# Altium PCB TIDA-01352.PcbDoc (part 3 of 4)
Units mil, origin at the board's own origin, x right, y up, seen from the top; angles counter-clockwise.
Board outline 6496.06 x 8661.42 mil, 4 copper layers (Top Layer, GND, PWR, Bottom Layer), stack 79.834 mil thick; 456 components, 240 nets, 1197 pads, 446 vias.
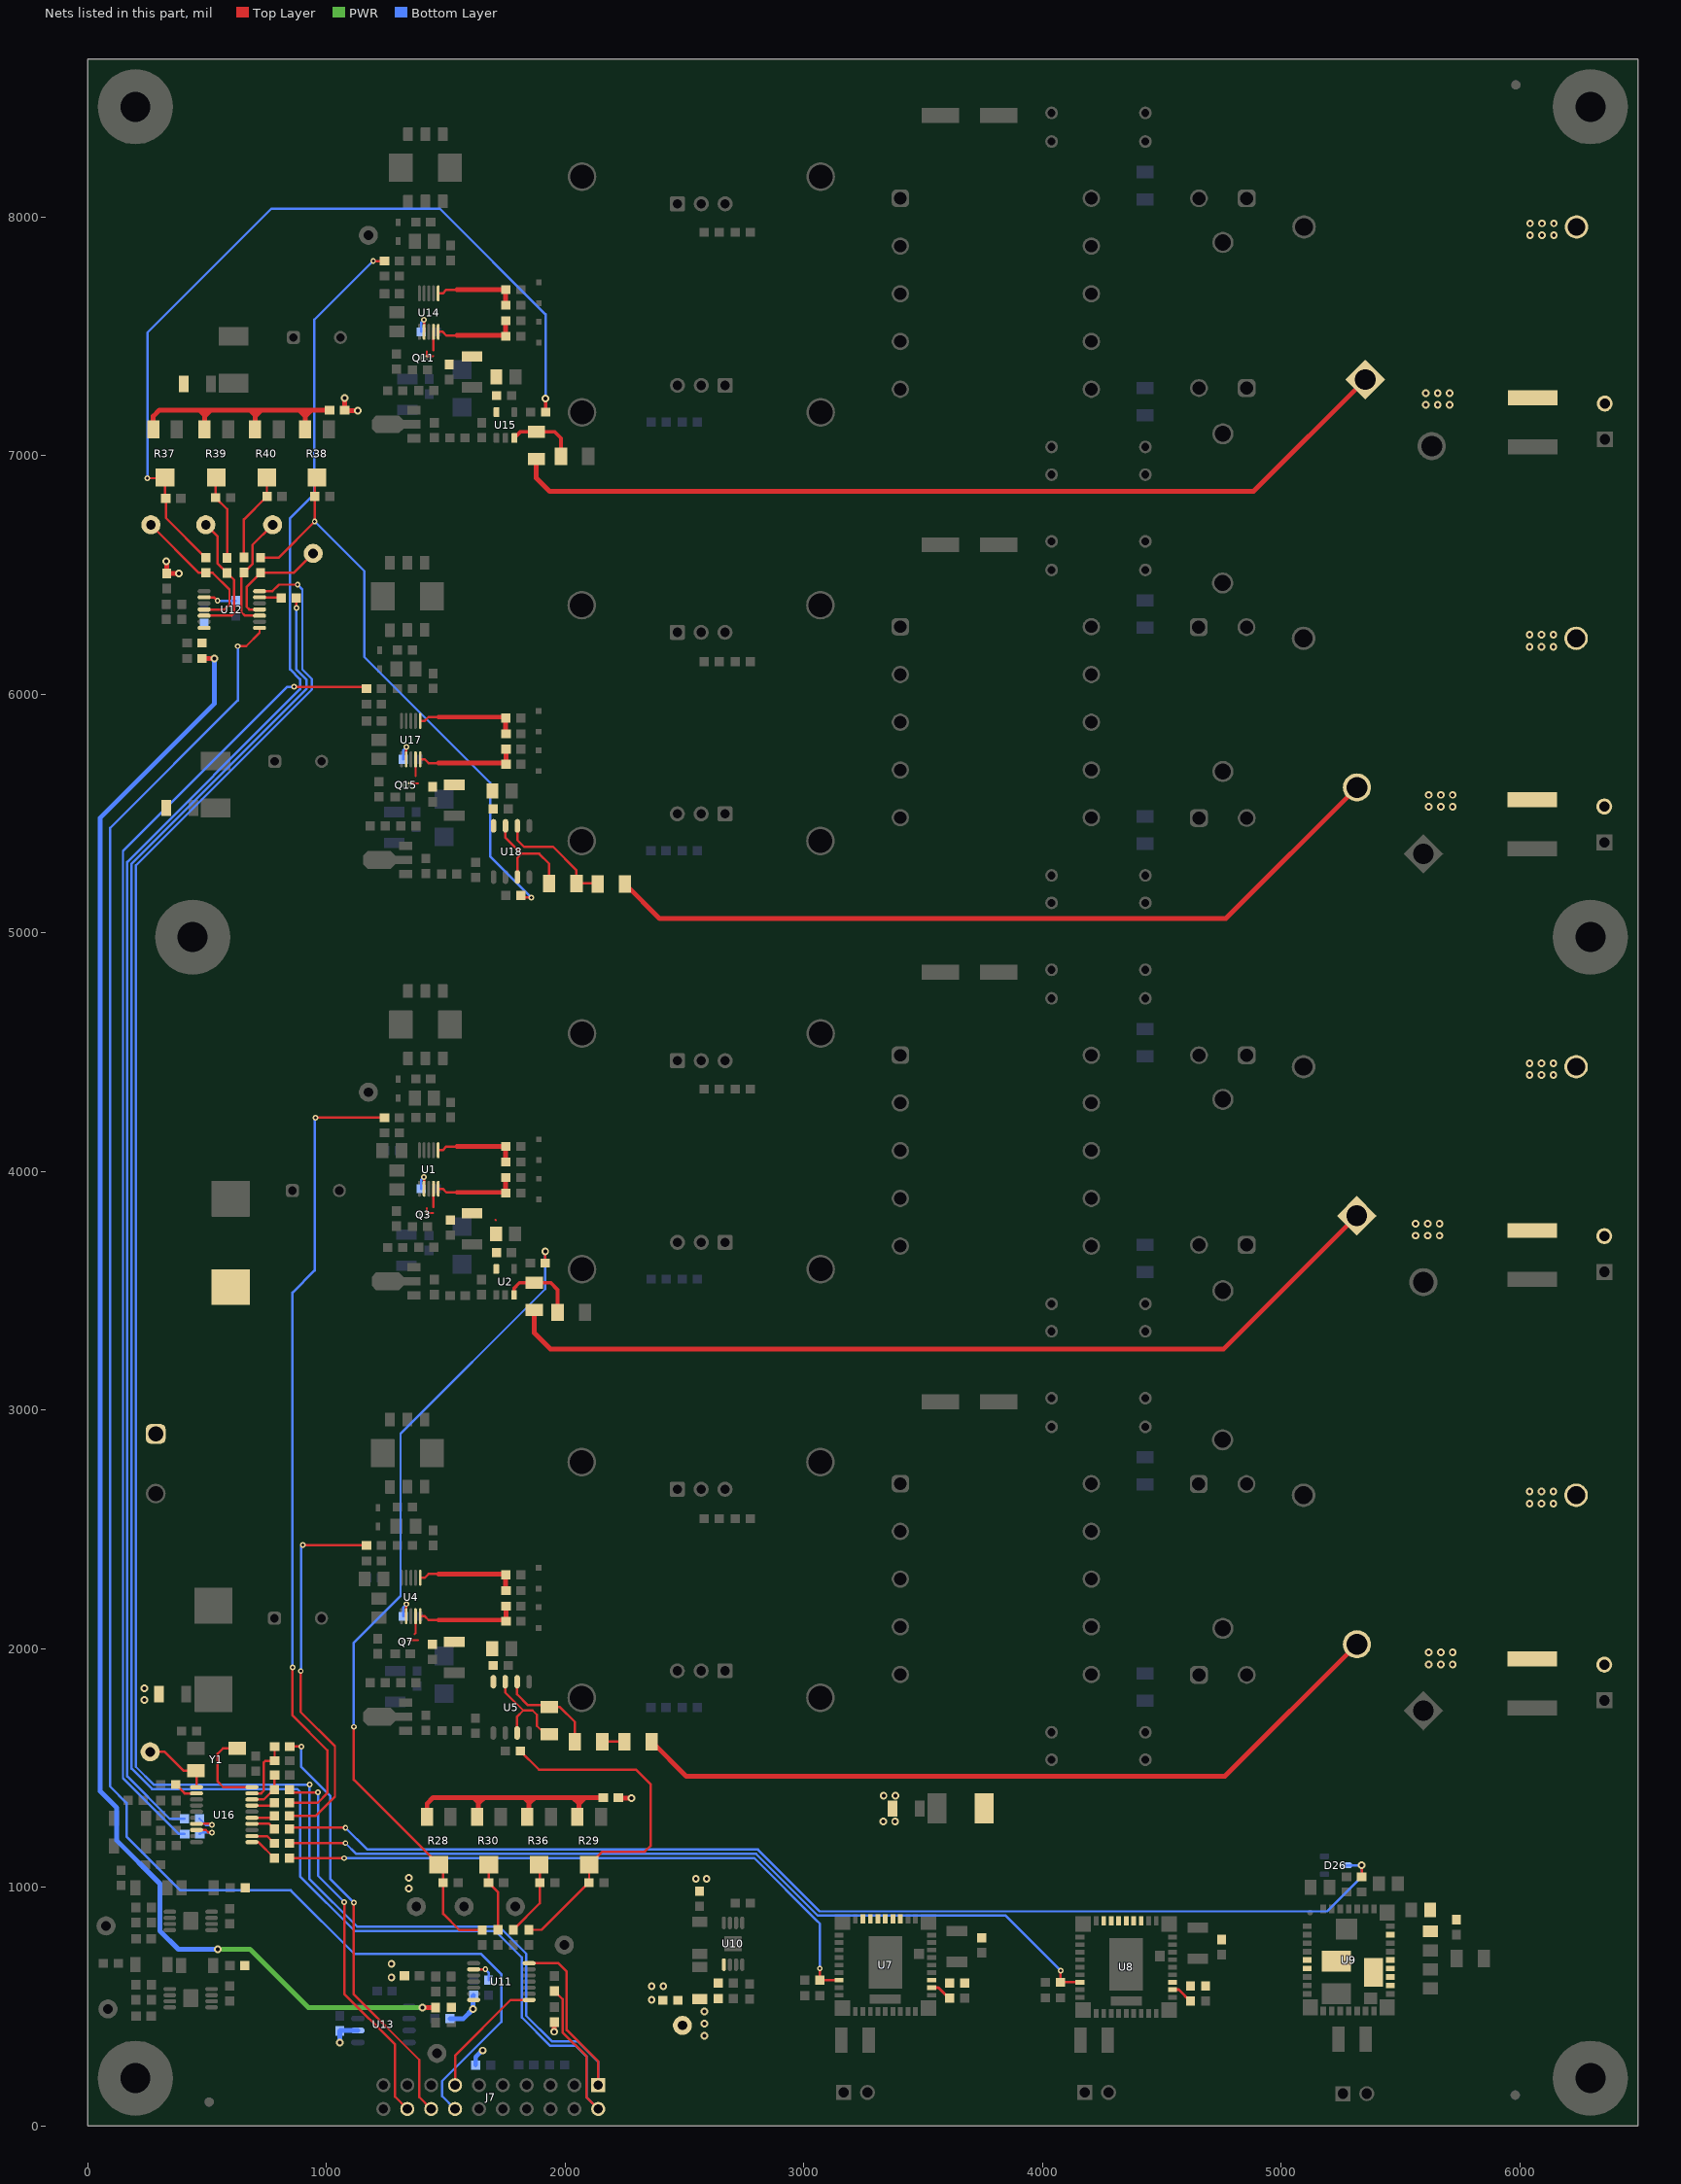
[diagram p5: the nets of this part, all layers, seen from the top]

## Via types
v1: diameter 32, hole 16, Top Layer to Bottom Layer, tented both sides, 325 vias
v2: diameter 19.68, hole 7.87, Top Layer to Bottom Layer, 75 vias
v3: diameter 24, hole 12, Top Layer to Bottom Layer, tented both sides, 46 vias

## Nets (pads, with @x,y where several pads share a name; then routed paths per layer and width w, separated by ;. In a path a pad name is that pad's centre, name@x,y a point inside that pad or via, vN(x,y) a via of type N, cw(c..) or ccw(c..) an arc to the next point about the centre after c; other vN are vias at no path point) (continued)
NetR28_3: R28.3 R29.3 R30.3 R36.3 R150.1 | length 1241.2
  Top Layer w20: R28.3@1422.04,1295.03 1422.04,1350.73 1447.05,1375.74 1637.05,1375.74 ; 1617.04,1375.74 1637.04,1355.74 1642.05,1355.74 1662.05,1375.74 ; R30.3@1637.04,1295.03 1637.04,1375.73 ; 1828.66,1375.74 1848.66,1355.74 1853.67,1355.74 1873.67,1375.74 ; R36.3@1848.66,1295.03 1848.66,1374.13 1847.05,1375.74 ; 2046.16,1363.24 2071.16,1363.24 ; R29.3@2058.66,1295.03 2058.66,1350.74 ; R150.1@2160.56,1375.74 2083.66,1375.74 ; 1637.05,1375.74 1662.05,1375.74 ; 1662.05,1375.74 1847.05,1375.74 ; 1847.05,1375.74 1848.67,1375.74 1873.67,1375.74 ; 1873.67,1375.74 2033.66,1375.74 ; 2033.66,1375.74 2083.66,1375.74 ; 2033.66,1375.74 2058.66,1350.74 ; 2058.66,1350.74 2083.66,1375.74
NetR32_2: R32.2 U12.11 VCON-B2.1 | length 479.8
  Top Layer w10: U12.11@720.24,6354.71 677.35,6354.71 665.76,6366.3 665.76,6449.26 R32.2@725,6508.5 863.5,6508.5 VCON-B2.1@945,6590
NetR33_2: R33.2 U12.10 VCON-D2.1 | length 496.2
  Top Layer w10: R33.2@644.1,6508.21 644.1,6343.96 658.94,6329.12 U12.10@720.24,6329.12 ; R33.2@655,6510 690,6545 690,6625 VCON-D2.1@775,6710
NetR34_2: R34.2 U12.5 VCON-C2.1 | length 549.3
  Top Layer w10: U12.5@487.96,6329.12 602.02,6329.12 614.1,6341.2 614.1,6478.21 R34.2@584.1,6508.21 545,6547.32 545,6660 VCON-C2.1@495,6710
NetR35_2: R35.2 U12.4 VCON-A2.1 | length 618.7
  Top Layer w10: VCON-A2.1@265,6710 466.5,6508.5 R35.2@495,6508.5 523.81,6508.5 594.1,6438.21 594.1,6376.2 572.61,6354.71 U12.4@487.96,6354.71
NetR37_3: R37.3 R38.3 R39.3 R40.3 R151.1 | length 1245.2
  Top Layer w20: R37.3@274.99,7109.29 274.99,7164.99 300,7190 490,7190 ; 469.99,7190 489.99,7170 495,7170 515,7190 ; R39.3@489.99,7109.29 489.99,7189.99 ; 681.61,7190 701.61,7170 706.61,7170 726.61,7190 ; R40.3@701.61,7109.29 701.61,7188.39 700,7190 ; 899.11,7177.5 924.11,7177.5 ; R38.3@911.61,7109.29 911.61,7165 ; R151.1@1010.71,7192.8 R151.1@1013.5,7190 936.61,7190 ; 490,7190 515,7190 ; 515,7190 700,7190 ; 700,7190 701.61,7190 726.61,7190 ; 726.61,7190 886.61,7190 ; 886.61,7190 936.61,7190 ; 886.61,7190 911.61,7165 ; 911.61,7165 936.61,7190
NetR48_2: R48.2 R49.1 U4.5 | length 429.8
  Top Layer w10: U4.5@1393.5,2135.72 1412.13,2135.72 1428,2119.85 1470.5,2119.85
  Top Layer w20: 1470.5,2119.85 1747.77,2119.85 R49.1@1751.65,2123.74 ; R49.1@1752.65,2115.11 R48.2@1752.65,2178.54
NetR50_1: R50.1 R51.2 U4.6 | length 432.8
  Top Layer w10: U4.6@1393.5,2297.13 1412.13,2297.13 1428,2313 1470.5,2313
  Top Layer w20: 1470.5,2313 1747.77,2313 R50.1@1751.65,2309.11 1751.65,2244.11 R51.2@1752.65,2243.11
NetR53_2: R53.2 U4.2 | length 108.9
  Top Layer w10: U4.2@1334.44,2135.72 1334.44,2184.87 1336,2186.43 v3(1336,2187)
  Bottom Layer w10: R53.2@1322.63,2135.72 1322.63,2173.94 1335.69,2187 v3(1336,2187)
NetR56_1: R56.1 R170.1 | length 92.8
  Top Layer w10: R170.1@2156.09,1610 R56.1@2248.91,1610
NetR59_1: R59.1 U5.3 U5.7 | length 434.4
  Top Layer w10: U5.7@1749.46,1861.28 1749.46,1816.54 1825,1741 ; U5.3@1799.46,1646.72 1799.46,1715.46 1825,1741 ; R59.1@1934,1640.91 1917.09,1640.91 1882,1676 1882,1723 1864,1741 1825,1741
NetR59_2: R59.2 R170.2 U5.6 | length 425.5
  Top Layer w10: U5.6@1799.46,1861.28 1799.46,1808.54 1845,1763 1926.09,1763 R59.2@1934,1755.09 1978.91,1755.09 2041.91,1692.09 R170.2@2041.91,1610
NetR67_2: R67.2 R68.1 U1.5 | length 354.3
  Top Layer w10: U1.5@1468.5,3927.29 1487.71,3927.29 1503,3912 1546.5,3912
  Top Layer w20: 1546.5,3912 R68.1@1751.5,3912 ; R68.1@1751.5,3909 R67.2@1751.5,3974
NetR69_1: R69.1 R70.2 U1.6 | length 354.3
  Top Layer w10: U1.6@1468.5,4088.71 1487.71,4088.71 1503,4104 1546.5,4104
  Top Layer w20: 1546.5,4104 R69.1@1751.5,4104 R70.2@1751.5,4039
NetR72_2: R72.2 U1.2 | length 104.1
  Top Layer w10: v3(1409,3976.88) 1409.44,3976.44 U1.2@1409.44,3927.29
  Bottom Layer w10: R72.2@1397.63,3927.29 1397.63,3965.51 v3(1409,3976.88)
NetR74_1: R74.1 R77.2 U2.3 | length 326.5
  Top Layer w15: U2.3@1786.4,3482.87 1786.4,3510.4 1809.09,3533.09 R74.1@1871,3533.09 1939.91,3533.09 1968.91,3504.09 R77.2@1968.91,3409
NetR88_2: R88.2 R89.1 U17.5 | length 429.8
  Top Layer w10: U17.5@1393.5,5726.72 1412.13,5726.72 1428,5710.86 1470.5,5710.86
  Top Layer w20: 1470.5,5710.86 1747.77,5710.86 R89.1@1751.65,5714.75 ; R89.1@1752.65,5706.12 R88.2@1752.65,5769.54
NetR90_1: R90.1 R91.2 U17.6 | length 432.8
  Top Layer w10: U17.6@1393.5,5888.14 1412.13,5888.14 1428,5904.01 1470.5,5904.01
  Top Layer w20: 1470.5,5904.01 1747.77,5904.01 R90.1@1751.65,5900.12 1751.65,5835.12 R91.2@1752.65,5834.12
NetR93_2: R93.2 U17.2 | length 108.9
  Top Layer w10: U17.2@1334.44,5726.72 1334.44,5775.87 1336,5777.43 v3(1336,5778.01)
  Bottom Layer w10: R93.2@1322.63,5726.72 1322.63,5764.94 1335.69,5778.01 v3(1336,5778.01)
NetR96_1: R96.1 R99.1 U18.6 | length 504
  Top Layer w10: U18.6@1800.56,5447.98 1800.56,5388.44 1829,5360 1950,5360 2048.09,5261.91 R99.1@2048.09,5207 2134.91,5207 R96.1@2136.91,5205
NetR99_2: R99.2 U18.3 U18.7 | length 465.1
  Top Layer w10: U18.7@1750.56,5447.98 1750.56,5398.44 1817.91,5331.09 ; U18.3@1800.56,5233.42 1800.56,5313.73 1817.91,5331.09 ; R99.2@1933.91,5207 1933.91,5289.09 1891.91,5331.09 1817.91,5331.09
NetR109_2: R109.2 R110.1 U14.5 | length 354.3
  Top Layer w10: U14.5@1468.5,7518.3 1487.71,7518.3 1503,7503.01 1546.5,7503.01
  Top Layer w20: 1546.5,7503.01 R110.1@1751.5,7503.01 ; R110.1@1751.5,7500.01 R109.2@1751.5,7565.01
NetR111_1: R111.1 R112.2 U14.6 | length 354.3
  Top Layer w10: U14.6@1468.5,7679.72 1487.71,7679.72 1503,7695.01 1546.5,7695.01
  Top Layer w20: 1546.5,7695.01 R111.1@1751.5,7695.01 R112.2@1751.5,7630.01
NetR114_2: R114.2 U14.2 | length 106.7
  Top Layer w10: v3(1409.1,7569.2) 1409.44,7568.87 U14.2@1409.44,7518.3
  Bottom Layer w10: R114.2@1397.63,7518.3 1397.63,7557.73 v3(1409.1,7569.2)
NetR116_1: R116.1 R119.2 U15.3 | length 294.5
  Top Layer w15: U15.3@1787.52,7073.8 1813.8,7100.09 R116.1@1880,7100.09 1955.91,7100.09 1982.91,7073.09 R119.2@1982.91,6996
NetR126_1: R126.1 U12.13 | length 92.5
  Top Layer w10: U12.13@720.24,6405.89 808.92,6405.89 R126.1@811.61,6403.2
NetR131_2: R131.2 U16.17 | length 98.9
  Top Layer w10: U16.17@688.17,1342.45 770.98,1342.45 R131.2@782.39,1353.86
NetR132_2: R132.2 U16.15 | length 97.4
  Top Layer w10: U16.15@688.17,1291.27 774.8,1291.27 R132.2@782.39,1298.86
NetR133_2: R133.2 U16.14 | length 103.3
  Top Layer w10: U16.14@688.17,1265.68 760.57,1265.68 R133.2@782.39,1243.86
NetR134_2: R134.2 U16.7 | length 129.8
  Top Layer w10: U16.7@455.89,1265.68 516.32,1265.68 v3(521,1261)
  Bottom Layer w10: R134.2@468.99,1287 494.99,1261 v3(521,1261)
NetR135_2: R135.2 U16.8 | length 123.7
  Top Layer w10: U16.8@455.89,1240.09 495.3,1240.09 506.39,1229 v3(521,1229)
  Bottom Layer w10: R135.2@469.5,1223 475.5,1229 v3(521,1229)
NetR136_2: R136.2 U16.12 | length 107
  Top Layer w10: U16.12@688.17,1214.5 752.01,1214.5 R136.2@782.5,1184
NetR137_2: R137.2 U16.11 | length 122
  Top Layer w10: U16.11@688.17,1188.91 715.6,1188.91 R137.2@782.5,1122
NetR138_2: R138.2 U16.2 | length 101.8
  Top Layer w10: R138.2@369.39,1430.5 406.25,1393.63 U16.2@455.89,1393.63
NetR142_2: R142.2 R144.2 U16.19 | length 281.2
  Top Layer w10: U16.19@688.17,1393.63 727.02,1393.63 738.37,1404.97 738.37,1523.37 745,1530 R144.2@783.5,1530 R142.2@783.5,1590
NetR143_2: R143.2 R145.2 U16.18 | length 168.6
  Top Layer w10: U16.18@688.17,1368.04 737.43,1368.04 R143.2@778.25,1408.86 ; R143.2@782.39,1408.86 782.39,1468.89 R145.2@783.5,1470
NetR146_1: R146.1 R147.2 U9.27
NetR148_1: R148.1 U11.2 | length 100.1
  Top Layer w10: U11.2@1617.19,655.82 v3(1666.26,655.82)
  Bottom Layer w10: v3(1666.26,655.82) 1680,642.07 R148.1@1680,610.5
NetR149_1: R149.1 U12.2 | length 138.3
  Top Layer w10: U12.2@487.96,6405.89 529.38,6405.89 v3(544.1,6391.17)
  Bottom Layer w10: v3(544.1,6391.17) 619.67,6391.17 R149.1@620,6391.5
NetR168_2: R168.2 U7.23 | length 90.1
  Top Layer w12: U7.23@3536.01,579.24 3564.26,579.24 R168.2@3608,535.5
NetR169_2: R169.2 U8.23 | length 93.5
  Top Layer w12: U8.23@4545.01,570.51 4571.99,570.51 R169.2@4619,523.5
NetU7_34: U7.34 U7.35 U7.36 U7.37 U7.38 U7.39
NetU8_34: U8.34 U8.35 U8.36 U8.37 U8.38 U8.39
NetU9_6: U9.6 U9.7 U9.21 U9.22 U9.23 U9.24 U9.38 U9.41
NetU16_20: U16.20 Y1.1 | length 360.9
  Top Layer w10: Y1.1@626.61,1582.24 567.24,1582.24 545,1560 545,1442.92 568.7,1419.22 U16.20@688.17,1419.22
SCL: J7.18 R143.1 | length 1607.3
  Top Layer w10: R143.1@845.39,1408.86 857.24,1397 964,1397 v3(965,1398) ; v3(1075,938.43) 1075,553.29 1288,340.29 1288,121.89 J7.18@1339.26,70.63
  Bottom Layer w10: v3(965,1398) 965,1048.43 v3(1075,938.43)
SCLK: J7.1 U11.14 U12.14 | length 9089.3
  Top Layer w10: U12.14@720.24,6431.48 773.83,6431.48 801.35,6459 v3(880,6459) ; U11.14@1849.48,681.41 1972.48,681.41 2007.37,646.52 2007.37,401.52 2139.26,269.63 J7.1@2139.26,170.63
  Bottom Layer w10: v3(880,6459) 899.6,6439.4 899.6,6103.4 940.03,6062.97 940.03,6019.97 202,5281.94 202,1505 277,1430 v3(930,1430) 930,1034 1129.37,834.63 1724.37,834.63 1837.26,721.74 1837.26,461.81 1944.43,354.63 2051.71,354.63 2139.26,267.09 J7.1@2139.26,170.63
SDA: J7.16 R142.1 | length 1793.3
  Top Layer w10: R142.1@846.5,1590 v3(895,1590) ; v3(1114.89,936) 1114.89,551.11 1389.26,276.74 1389.26,120.63 J7.16@1439.26,70.63
  Bottom Layer w10: v3(895,1590) 895,1503.99 1016,1382.99 1016,1034.89 v3(1114.89,936)
SDIN: J7.2 R9.2 R126.2 | length 8798.6
  Top Layer w10: v3(874.6,6360.7) R126.2@874.6,6403.2 ; R9.2@1955.36,565.14 1989.37,531.13 1989.37,392.52 2090.26,291.63 2090.26,119.63 J7.2@2139.26,70.63
  Bottom Layer w10: v3(874.6,6360.7) 874.6,6102.86 917.1,6060.35 917.1,6022.5 184,5289.39 184,1497.54 269.54,1412 878,1412 890,1400 890,1046 1119.37,816.63 1708.26,816.63 1819.26,705.63 1819.26,454.35 1936.97,336.63 2044.26,336.63 2090.26,290.63 2090.26,119.63 J7.2@2139.26,70.63
SDO1: J7.13 U11.8 | length 530.8
  Top Layer w10: J7.13@1539.26,170.63 1539.26,294.63 1772.48,527.86 U11.8@1849.48,527.86
SDO2: J7.14 U12.8 | length 7873
  Top Layer w10: v3(629.1,6201.2) 664.1,6201.2 720.24,6257.35 U12.8@720.24,6277.94
  Bottom Layer w10: v3(629.1,6201.2) 629.1,5974.1 94,5439 94,1422.65 163,1353.65 163,1213 389,987 851,987 1116.37,721.63 1647.26,721.63 1733.22,635.67 1733.22,435.6 1485.19,187.56 1485.19,124.7 J7.14@1539.26,70.63
SYNC: SYNC.1 U16.1 Y1.3 | length 330
  Top Layer w10: SYNC.1@284.39,1545 SYNC.1@261.89,1567.5 322.5,1567.5 402.24,1487.76 Y1.3@453.39,1487.76 Y1.3@455.89,1485.25 ; U16.1@455.89,1419.22 Y1.3@455.89,1485.25 ; Y1.3@455.89,1489.31 Y1.3@455.89,1485.25
SYNC1: C60.2 R131.1 | length 3396.5
  Top Layer w10: R131.1@845.39,1353.86 963.86,1353.86 1004,1394 1004,1574 858.26,1719.74 v3(858.26,1920.58) ; v3(955,4225) 1240.24,4225 1242.24,4223 C60.2@1243.5,4224.27
  Bottom Layer w10: v3(858.26,1920.58) 858.26,3492.11 951.15,3585 951.15,4221.15 v3(955,4225)
SYNC2: C48.2 R132.1 | length 1608.9
  Top Layer w10: R132.1@845.39,1298.86 954.86,1298.86 1036,1380 1036,1591 892.53,1734.47 v3(892.53,1906) ; v3@902.31,2432.69 C48.2@1168.5,2432.69
  Top Layer w20: v3(901.15,2433.85) v3@902.31,2432.69
  Bottom Layer w10: v3(892.53,1906) 895,1908.47 895,2427.69 v3(901.15,2433.85)
SYNC3: R6.2 R137.1 U7.8 | length 2653.9
  Top Layer w10: R137.1@845.5,1122 v3(1075,1122) ; v3@3067.11,659.23 R6.2@3067.11,610.73 U7.8@3148.21,610.74
  Top Layer w15: v3@3067.11,659.23 v3(3067.61,659.73)
  Bottom Layer w10: v3(1075,1122) 2793.09,1122 3052.09,863 3067.61,847.5 v3(3067.61,659.73)
SYNC4: R13.2 R136.1 U8.8 | length 3583
  Top Layer w10: R136.1@845.5,1184 846.5,1185 v3(1080,1185) ; v3@4076.11,650.5 R13.2@4076.11,602 U8.8@4157.21,602.01
  Top Layer w15: v3@4076.11,650.5 v3(4076.61,651)
  Bottom Layer w10: v3(1080,1185) 1125,1140 2800.54,1140 3059.54,881 3846.61,881 v3(4076.61,651)
SYNC5: C133.2 D26.3 R133.1 | length 4858.6
  Top Layer w10: R133.1@845.39,1243.86 851.53,1250 v3(1080,1250) ; C133.2@5337.5,1044 v1(5337.5,1092.5)
  Bottom Layer w10: v3(1080,1250) 1172,1158 2808,1158 3067,899 5192.5,899 5337.5,1043.99 v1(5337.5,1092.5) 5337,1092 D26.3@5276.24,1092
SYNC6: C86.2 R134.1 | length 7174.2
  Top Layer w10: v3@1196.86,7815.27 C86.2@1243.5,7815.27
  Top Layer w20: v3(1196,7816.13) v3@1196.86,7815.27
  Bottom Layer w10: R134.1@406,1287 343.91,1287 166,1464.91 166,5296.85 890,6020.85 890,6062 848,6104 848,6738 950,6840 950,7570.13 v3(1196,7816.13)
SYNC7: C73.2 R135.1 | length 5545.5
  Top Layer w10: v3@870.1,6031.2 1160.01,6031.2 C73.2@1167.51,6023.7 ; C73.2@1168.08,6023.13 C73.2@1167.51,6023.7 ; C73.2@1168.5,6023.7 C73.2@1167.51,6023.7
  Bottom Layer w10: R135.1@406.5,1223 382.46,1223 148,1457.46 148,5343 836.2,6031.2 v3(865,6031.2)
VADJ_3V3: R8.2 R168.1 U7.24
VADJ_5V: R17.2 R169.1 U8.24
VCC-N1: C46.1 C51.1 C52.1 C117.1 Q7.2 U4.4 U5.8 | length 114.1
  Top Layer w8: Q7.2@1347.92,2035.32 1384.32,2035.32 ; 1369,2060 1373.81,2064.81 U4.4@1373.81,2135.72
VCC-N2: C71.1 C76.1 C77.1 C127.1 Q15.2 U17.4 U18.8 | length 107.3
  Top Layer w8: Q15.2@1347.92,5626.32 1384.32,5626.32 ; 1373.81,5655.82 U17.4@1373.81,5726.72
VCC-P1: C58.1 C63.1 C64.1 C122.1 Q3.2 U1.4 U2.5 | length 127.7
  Top Layer w8: 1420.8,3845.2 Q3.2@1420.8,3825.16 1447.84,3825.16 1448,3825 ; 1708,3798 1711,3795
  Top Layer w10: 1448.81,3851.19 U1.4@1448.81,3927.29
VCC-P2: C84.1 C89.1 C90.1 C132.1 Q11.2 U14.4 U15.5 | length 123.4
  Top Layer w8: 1420.8,7436.21 Q11.2@1420.8,7416.16 1447.84,7416.16 1448,7416.01
  Top Layer w10: 1448.81,7442.2 U14.4@1448.81,7518.3
VCON-A1: C14.1 R25.1 R28.2 R79.2 | length 3503
  Top Layer w10: v3(1115,1672) 1115,1450.5 R28.2@1471.26,1094.24 1489.5,1075.99 C14.1@1489.5,1019.63 1489.5,888.13 1556.5,821.13 R25.1@1653.33,821.13 ; v1(1917,3664) 1917.5,3663.5 R79.2@1917.5,3616
  Bottom Layer w10: v3(1115,1672) 1115,2025 1311,2221 1311,2901 1917,3507 v1(1917,3664)
VCON-A2: C15.1 R35.1 R37.2 R121.2 | length 3569.9
  Top Layer w10: v3(250,6905) 320.7,6905 R37.2@324.2,6908.5 324.2,6823.99 C15.1@327.4,6820.8 327.4,6739.09 R35.1@495,6571.5
  Top Layer w15: R121.2@1918.62,7181.94 v1@1918.62,7238.44
  Bottom Layer w10: v3(250,6905) 250,7515 770,8035 1475,8035 1918.12,7591.88 v1(1918.12,7238.94)
VCON-B1: C93.1 R22.1 R29.2 R60.2 | length 1559.6
  Top Layer w10: R60.2@1812.45,1571.05 1890.5,1493 2297,1493 2358,1432 2358,1173 2334,1149 2156.02,1149 R29.2@2101.26,1094.24 2101.26,1021.13 C93.1@2099.76,1019.63 1901.62,821.5 R22.1@1849,821.5
VCON-B2: C96.1 R32.1 R38.2 R100.2 | length 2497.9
  Top Layer w10: R32.1@725,6571.5 799.4,6571.5 v3(951.32,6723.42) C96.1@951.32,6828.9 951.32,6899.01 R38.2@960.82,6908.5 ; R100.2@1828.9,5171 R100.2@1814.6,5156.7 1823.3,5148 v3(1859,5148)
  Bottom Layer w10: v3(951.32,6723.42) 1159.1,6515.64 1159.1,6156.2 1686.1,5629.2 1686.1,5320.9 v3(1859,5148)
VCON-C1: C92.1 R24.1 R30.2 | length 289.6
  Top Layer w10: R30.2@1681.26,1094.24 1681.26,1021.13 C92.1@1679.76,1019.63 1719,980.39 R24.1@1719,821.5
VCON-C2: C95.1 R34.1 R39.2 | length 358.8
  Top Layer w10: R39.2@539.2,6908.5 535.7,6905 C95.1@535.7,6823.9 584.1,6775.5 R34.1@584.1,6571.2
VCON-D1: C16.1 R23.1 R36.2 | length 319.9
  Top Layer w10: R23.1@1783,821.5 1894,932.5 C16.1@1894,1019.63 1894,1091.5 R36.2@1891.26,1094.24
VCON-D2: C94.1 R33.1 R40.2 | length 375.6
  Top Layer w10: R33.1@655,6572.99 655,6732.58 C94.1@751.32,6828.9 750.82,6829.4 R40.2@750.82,6908.5
VDD_5.3V: C34.1 L5.1 L8.1 R19.1 R150.2 R151.2 U13.2 | length 389.2
  Top Layer w20: v1(329.76,6557.3) 330.76,6556.3 L8.1@330.76,6505.8 381.25,6505.8 v1(381.76,6506.3) ; v1(1076.5,7240.5) R151.2@1076.5,7190 1078.5,7188 v1(1131,7188) ; R150.2@2223.55,1375.74 2225.55,1373.74 v1(2278.05,1373.74)
  Bottom Layer w20: v1(1056.26,349.63) C34.1@1056.26,398.14 1057.75,399.63 U13.2@1132.08,399.63
  other v1: 2363,529 2363,586 2411.8,586.02 1273,622 1273,679
VDD_5V3: C28.2 C29.1 R19.2 R20.1 R124.2 R125.1 U10.1 VDD_5V3.1 | length 127.2
  Top Layer w15: R19.2@2481.8,529.52 R19.2@2483.57,531.29 ; C29.1@2563.8,531.29 C29.1@2565.73,533.22
  Top Layer w20: v1@1652.26,318.63 v1(1655.26,315.63) ; v1(1954.26,394.63) 1954.26,435.84 R124.2@1955.36,434.74
  Bottom Layer w20: R125.1@1625.76,254.63 1625.76,289.14 1652.26,315.63 v1(1655.26,315.63)
  other v1: 2583.8,377.02 2583.8,428.02 2583.8,479.02
VIN: F1.2 J1.1 R3.1 R4.1 R80.1 R101.1
  other v1: 3333.61,1276 3383,1276 3334.6,1384 3384,1384 238,1785 238,1833.54
VIN1: F3.1 R1.2 R5.2 R10.2 R11.2 R18.2 R127.2
  other v1: 1346.26,994.63 2548.11,1035 2593.11,1035 1346.26,1039.63
VOUT-N1: C42.2 C114.1 J3.2 L3.2 R56.2 | length 3243.9
  Top Layer w20: R56.2@2363.09,1610 2508.09,1465 4764.61,1465 C42.2@5317.81,2018.19
  other v1: 5619,1934 5669,1934 5719,1934 5619,1984 5669,1984 5719,1984 6041,2607.99 6091,2607.99 6141,2607.99 6041,2657.99 6091,2657.99 6141,2657.99
VOUT-N2: C67.2 C124.1 J9.2 L7.2 R96.2 | length 3354.3
  Top Layer w20: R96.2@2251.09,5205 2396.09,5060 4768.61,5060 C67.2@5317.81,5609.19
  other v1: 5619,5528 5669,5528 5719,5528 5619,5578 5669,5578 5719,5578 6041,6199 6091,6199 6141,6199 6041,6249 6091,6249 6141,6249
VOUT-P1: C54.1 C119.1 J2.2 L2.2 R74.2 | length 3801.4
  Top Layer w20: R74.2@1871,3418.91 1871,3323 1938,3256 4759.32,3256 C54.1@5317.51,3814.19
  other v1: 5564,3731 5614,3731 5664,3731 5564,3781 5614,3781 5664,3781 6041,4403.5 6091,4403.5 6141,4403.5 6041,4453.5 6091,4453.5 6141,4453.5
VOUT-P2: C80.1 C129.1 J8.2 L6.2 R116.2 | length 3770.4
  Top Layer w20: R116.2@1880,6985.91 1880,6905 1935,6850 4884.61,6850 C80.1@5352.81,7318.19
  other v1: 5606,7212 5656,7212 5706,7212 5606,7262 5656,7262 5706,7262 6043,7922.99 6093,7922.99 6143,7922.99 6043,7972.99 6093,7972.99 6143,7972.99
VREF_5V: C32.1 C33.1 C40.1 C41.1 R21.2 R27.1 R31.2 U11.7 U12.7 | length 7145.3
  Top Layer w20: C40.1@479.6,6149.71 530.97,6149.71 v1(531.57,6149.11) ; v1@1403.95,495.51 C32.1@1457.6,495.51
  PWR w20: v1(545,740) 680,740 923.82,496.18 v1(1403.28,496.18)
  Bottom Layer w20: v1(531.57,6149.11) 531.57,5960.67 53,5482.1 53,1402 122,1333 122,1196.02 303.02,1015 303.02,816.98 380,740 v1(545,740) ; R27.1@1517.64,449.63 1574.37,449.63 v1(1614.37,489.63) 1614.37,544.72 R21.2@1617.19,547.55
pads on no net: FID1.1 FID2.1 FID3.1 FID4.1 FID5.1 FID6.1 H1.1 H2.1 H3.1 H4.1 H5.1 H6.1 H7.1 H7.2 H8.0 H9.0 H10.0 H11.0 H12.0 H12.1 H12.2 H13.0 H13.1 H14.1 H15.1 H15.2 H16.1 H16.2 H17.1 H18.1 H19.1 H19.2 H20.1 H20.2 H21.1 H22.1 H23.1 H23.2 H24.1 H24.2 J7.11 LBL1.0 Q3.0 Q7.0 Q11.0 Q15.0 T1.2 T1.4 T1.7 T1.9 T2.2 T2.4 T2.7 T2.9 T3.2 T3.4 T3.7 T3.9 T4.2 T4.4 T4.5 T4.6 T5.2 T5.4 T5.5 T5.6 T6.2 T6.4 T6.5 T6.6 T7.2 T7.4 T7.7 T7.9 T8.2 T8.4 T8.5 T8.6 U3.3 U3.7 U6.3 U6.7 U7.6 U7.10 U7.20 U7.21 U7.25 U7.40 U8.6 U8.10 U8.20 U8.21 U8.25 U8.40 U9.2 U9.3 U9.25 U9.28 U9.35 U10.3 U10.7 U13.1 U13.3 U13.7 U13.8 U16.4

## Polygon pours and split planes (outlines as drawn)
VOUT-N1 on Top Layer "Top Layer-No Net 1" (solid, pour order 1048): 32 vertices, not listed, extent 5251,1899 6408,2701
NetD3_3 on Top Layer "h" (solid, remove dead copper, pour order 1044): 4815,2624.5 4815,2719 4838,2742 5079,2742 5148,2673 5148,2008 4973.21,1833.21 4825,1833.21 4810,1848.21 4810,1959.5 4875,2024.5 4875,2564.5
NetD2_1 on Top Layer "h" (solid, remove dead copper, pour order 1040): 4815,4420 4815,4514.5 4838,4537.5 5079,4537.5 5148,4468.5 5148,3803.5 4973.21,3628.71 4825,3628.71 4810,3643.71 4810,3755 4875,3820 4875,4360
GND on Top Layer "Top Layer-No Net 1" (solid, pour order 1036): 6400,3613 5532.7,3613 5507.7,3588 5494.7,3575 5494.7,3553 5494.7,3492 5520.7,3466 5546.7,3440 5600.7,3440 6343.7,3440 6396.7,3493 6407.7,3504 6407.7,3530 6407.7,3605.3
VOUT-P1 on Top Layer "Top Layer-No Net 1" (solid, pour order 1034): 30 vertices, not listed, extent 5230,3693 6407.7,4497
GND on Top Layer "Top Layer-No Net 1" (solid, pour order 1024): 6401,1820 5536,1820 5508,1792 5495,1779 5495,1757 5495,1696 5521,1670 5547,1644 5601,1644 6344,1644 6397,1697 6408,1708 6408,1734 6408,1813
VOUT-N2 on Top Layer "Top Layer-No Net 1" (solid, pour order 1006): 32 vertices, not listed, extent 5251,5494 6408,6292
GND on Top Layer "Top Layer-No Net 1" (solid, pour order 1004): 6397,5415 5540,5415 5508,5383 5495,5370 5495,5348 5495,5287 5521,5261 5547,5235 5601,5235 6344,5235 6397,5288 6408,5299 6408,5325 6408,5404
VOUT-P2 on Top Layer "Top Layer-No Net 1" (solid, pour order 1000): 31 vertices, not listed, extent 5267,7183 6410,8028
GND on Top Layer "Top Layer-No Net 1" (solid, pour order 998): 6319,7103 6402,7103 6413,7092 6413,7034 6413,7014 6384,6985 6370,6971 5626,6971 5594,6971 5577,6988 5564,7001 5564,7055 5564,7090 5577,7103
NetC17_2 on Top Layer "h" (solid, remove dead copper, pour order 778): 22 vertices, not listed, extent 5438,624 5767,825
NetR146_1 on Top Layer "h" (solid, remove dead copper, pour order 776): 5445,790 5660,790 5670,800 5670,930 5660,940 5605,940 5600,935 5600,860 5553,813 5443,813 5440,810 5440,795
VIN on Top Layer "h" (solid, remove dead copper, pour order 774): 45 vertices, not listed, extent 37.33,1764 696,7345
NetF4_2 on Top Layer "Top Layer-MU" (solid, remove dead copper, pour order 772): 626.1,7347.2 476.1,7347.2 471.1,7342.2 471.1,7267.2 476.1,7262.2 676.1,7262.2 681.1,7267.2 681.1,7342.2 676.1,7347.2
NetC83_1 on Top Layer "h" (solid, remove dead copper, pour order 750): 23 vertices, not listed, extent 2535,7756.01 3445,8121.01
NetC83_2 on Top Layer "h" (solid, remove dead copper, pour order 748): 2733,7895.01 2628,7895.01 2623,7900.01 2623,7955.01 2623,7960.01 2628,7965.01 2733,7965.01 2738,7960.01 2738,7900.01
GND on Top Layer "h" (solid, remove dead copper, pour order 746): 2755,7921.01 2755,7996.01 2735,8016.01 2650,8016.01 2640,8026.01 2635,8031.01 2635,8076.01 2650,8091.01 2785,8091.01 2810,8066.01 2810,7901.01 2805,7896.01 2765,7896.01 2760,7896.01 2755,7901.01
NetC100_1 on Top Layer "h" (solid, remove dead copper, pour order 744): 29 vertices, not listed, extent 1460,7616.01 3655,8471.01
GND on Top Layer "h" (solid, remove dead copper, pour order 710): 2754.15,6125.12 2754.15,6200.12 2734.15,6220.12 2649.15,6220.12 2639.15,6230.12 2634.15,6235.12 2634.15,6280.12 2649.15,6295.12 2784.15,6295.12 2809.15,6270.12 2809.15,6105.12 2804.15,6100.12 2764.15,6100.12 2759.15,6100.12 2754.15,6105.12
NetC70_2 on Top Layer "h" (solid, remove dead copper, pour order 708): 2732.15,6099.12 2627.15,6099.12 2622.15,6104.12 2622.15,6159.12 2622.15,6164.12 2627.15,6169.12 2732.15,6169.12 2737.15,6164.12 2737.15,6104.12
NetC70_1 on Top Layer "h" (solid, remove dead copper, pour order 706): 23 vertices, not listed, extent 2534.15,5960.12 3444.15,6325.12
NetC99_1 on Top Layer "h" (solid, remove dead copper, pour order 704): 26 vertices, not listed, extent 1390,5820.5 3655,6675.5
VCC-N2 on Top Layer "h" (solid, remove dead copper, pour order 702): 22 vertices, not listed, extent 1340,5421.01 1725,5761.01
NetC97_1 on Top Layer "h" (solid, remove dead copper, pour order 700): 26 vertices, not listed, extent 1390,2229.5 3655,3084.5
NetC45_1 on Top Layer "h" (solid, remove dead copper, pour order 698): 23 vertices, not listed, extent 2534.15,2369.11 3444.15,2734.11
NetC45_2 on Top Layer "h" (solid, remove dead copper, pour order 696): 2732.15,2508.11 2627.15,2508.11 2622.15,2513.11 2622.15,2568.11 2622.15,2573.11 2627.15,2578.11 2732.15,2578.11 2737.15,2573.11 2737.15,2513.11
GND on Top Layer "h" (solid, remove dead copper, pour order 694): 2754.15,2534.11 2754.15,2609.11 2734.15,2629.11 2649.15,2629.11 2639.15,2639.11 2634.15,2644.11 2634.15,2689.11 2649.15,2704.11 2784.15,2704.11 2809.15,2679.11 2809.15,2514.11 2804.15,2509.11 2764.15,2509.11 2759.15,2509.11 2754.15,2514.11
NetC98_1 on Top Layer "h" (solid, remove dead copper, pour order 640): 29 vertices, not listed, extent 1460,4025 3655,4880
NetC57_2 on Top Layer "h" (solid, remove dead copper, pour order 636): 2733,4304 2628,4304 2623,4309 2623,4364 2623,4369 2628,4374 2733,4374 2738,4369 2738,4309
NetC57_1 on Top Layer "h" (solid, remove dead copper, pour order 634): 23 vertices, not listed, extent 2535,4165 3445,4530
VCC-N1 on Top Layer "h" (solid, remove dead copper, pour order 624): 22 vertices, not listed, extent 1340,1830 1725,2170
NetC79_1 on Top Layer "Top Layer-MU" (solid, remove dead copper, pour order 430): 37 vertices, not listed, extent 536.1,7309.2 1401,8265.01
NetC2_1 on Top Layer "Top Layer-MU" (solid, remove dead copper, pour order 428): 40 vertices, not listed, extent 515,3715 1401,4674
NetC3_1 on Top Layer "Top Layer-MU" (solid, remove dead copper, pour order 424): 37 vertices, not listed, extent 445,1923.2 1324.9,2882.42
NetC66_1 on Top Layer "Top Layer-MU" (solid, remove dead copper, pour order 420): 38 vertices, not listed, extent 461.1,5514.2 1326,6473.43
NetF5_2 on Top Layer "Top Layer-MU" (solid, remove dead copper, pour order 412): 551.1,5567.2 401.1,5567.2 396.1,5562.2 396.1,5487.2 401.1,5482.2 601.1,5482.2 606.1,5487.2 606.1,5562.2 601.1,5567.2
CLK_3.3V on Top Layer "Top Layer-MU" (solid, remove dead copper, pour order 406): 242,1050 262.89,1070.89 262.89,1117.5 260.89,1119.5 188.89,1119.5 170.89,1137.5 170.89,1197.5 161.89,1206.5 58.89,1206.5 52.89,1200.5 52.89,1072.11 75,1050
CLK_1.8V on Top Layer "Top Layer-MU" (solid, remove dead copper, pour order 404): 188.89,1385.5 188.89,1337.5 170.89,1319.5 170.89,1259.5 161.89,1250.5 44.5,1250.5 40,1255 40,1375 52.5,1387.5 183.89,1387.5 186.89,1387.5
GND on Top Layer "Top Layer-MU" (solid, remove dead copper, pour order 402): 27 vertices, not listed, extent 198.59,1139.82 484.59,1326.82
NetC105_1 on Top Layer "Top Layer-MU" (solid, remove dead copper, pour order 398): 485.89,1197.5 286.89,1197.5 283.89,1194.5 283.89,1070.5 285.89,1068.5 327.89,1068.5 334.89,1075.5 334.89,1138.14 343.62,1146.88 482.27,1146.88 487.89,1152.5 487.89,1195.5
NetC12_1 on Top Layer "Top Layer-MU" (solid, remove dead copper, pour order 396): 248.89,1386.5 388.51,1386.5 397.16,1377.85 398.51,1376.5 438.89,1376.5 479.89,1376.5 482.89,1373.5 482.89,1360.5 479.89,1357.5 404.89,1357.5 389.89,1342.5 212.89,1342.5 210.89,1344.5 210.89,1384.5 212.89,1386.5
GND on Top Layer "Top Layer-MU" (solid, remove dead copper, pour order 394): 23 vertices, not listed, extent 243.63,760.87 463.63,1030.9
NetC1_2 on Top Layer "Top Layer-MU" (solid, remove dead copper, pour order 392): 19 vertices, not listed, extent 98.37,891.17 368.37,1030.9
NetC102_1 on Top Layer "Top Layer-MU" (solid, remove dead copper, pour order 390): 507.37,1030.9 496.37,1019.9 496.37,896.9 500.33,892.94 546.41,892.94 550.37,896.9 550.37,958.9 553.37,961.9 618.37,961.9 623.91,967.44 623.91,1024.35 617.37,1030.9
VIN on Top Layer "Top Layer-MU" (solid, remove dead copper, pour order 388): 3323.11,1400 3408.11,1400 3420,1388.11 3420,1271.89 3408.11,1260 3320,1260 3313.11,1266.89 3313.11,1390
NetC9_1 on Top Layer "Top Layer-MU" (solid, remove dead copper, pour order 344): 502.98,704.53 491.98,693.53 491.98,570.53 495.94,566.57 542.02,566.57 545.98,570.53 545.98,632.53 548.98,635.53 613.98,635.53 619.52,641.07 619.52,697.99 612.98,704.53
VREF_5V on Top Layer "Top Layer-MU" (solid, remove dead copper, pour order 316): 1391.1,523 1387.28,519.18 1387.28,481.18 1391.28,477.18 1394.46,474 1431.23,474 1643,474 1649,480 1649,529.9 1646.72,532.18 1583.18,532.18 1574,523
GND on Top Layer "Top Layer-MU" (solid, remove dead copper, pour order 6): 5291.11,113 5278.11,100 5088.11,100 5078.11,110 5078.11,556 5083.11,561 5166.11,561 5170.11,565 5170.11,595 5172.11,597 5289.11,597 5291.11,595
A_VOUT on Top Layer "Top Layer-MU" (solid, remove dead copper, pour order 20): 5236.11,927 5236.11,875 5226.11,865 5341.11,865 5330.11,876 5330.11,890 5330.11,929 5327.11,932 5240.11,932 5236.11,928
NetC23_1 on Top Layer "Top Layer-MU" (solid, remove dead copper, pour order 24): 4447.57,757.4 4512.53,757.4 4512.53,739.08 4514.61,737 4773.11,737 4778.11,732 4778.11,662 4771.61,655.5 4449.61,655.5 4448.11,657 4447.57,657.54
VADJ_5V on Top Layer "Top Layer-MU" (solid, remove dead copper, pour order 26): 4712.11,611.5 4526.11,611.5 4526.11,564.25 4567.86,564.25 4706.11,564.25 4712.11,564.25
NetC18_1 on Top Layer "Top Layer-MU" (solid, remove dead copper, pour order 28): 4247.11,548 4247.11,507.5 4247.11,489 4247.11,107.5 4255.61,99 4413.11,99 4425,110.89 4425,501.89 4426.61,503.5 4461.11,503.5 4488.61,531 4563.61,531 4563.61,548 4277.11,548
GND on Top Layer "Top Layer-MU" (solid, remove dead copper, pour order 30): 48 vertices, not listed, extent 3961.11,99 4696.61,885.5
VADJ_3V3 on Top Layer "Top Layer-MU" (solid, remove dead copper, pour order 40): 3703.11,620.23 3517.11,620.23 3517.11,572.98 3558.86,572.98 3697.11,572.98 3703.11,572.98
NetC6_1 on Top Layer "Top Layer-MU" (solid, remove dead copper, pour order 44): 3438.57,766.13 3503.53,766.13 3503.53,747.82 3505.61,745.73 3764.11,745.73 3769.11,740.73 3769.11,670.73 3762.61,664.23 3440.61,664.23 3439.11,665.73 3438.57,666.28
GND on Top Layer "Top Layer-MU" (solid, remove dead copper, pour order 46): 48 vertices, not listed, extent 2952.11,107.73 3687.61,894.23
NetC4_1 on Top Layer "Top Layer-MU" (solid, remove dead copper, pour order 48): 22 vertices, not listed, extent 3129.61,108.73 3554.61,651.73
NetF3_2 on Top Layer "Top Layer-MU" (solid, remove dead copper, pour order 54): 3438.11,1395 3438.11,1270 3445.11,1263 3598.11,1263 3603.11,1268 3603.11,1393 3595.11,1401 3442.11,1401 3438.11,1397
NetC30_1 on Top Layer "Top Layer-MU" (solid, remove dead copper, pour order 56): 2674.8,871.02 2674.8,825.55 2671.51,822.26 2536.16,822.26 2526.4,832.02 2526.4,934.62 2530.8,939.02 2531.8,940.02 2549.8,940.02 2595.8,940.02 2598.8,937.02 2598.8,885.02 2603.8,880.02 2670.8,880.02 2674.8,876.02
GND on Top Layer "Top Layer-MU" (solid, remove dead copper, pour order 60): 21 vertices, not listed, extent 2487.8,575.02 2801.8,795.02
VDD_5V3 on Top Layer "Top Layer-MU" (solid, remove dead copper, pour order 64): 21 vertices, not listed, extent 2451.8,355.02 2673.8,704.26
VDD_5.3V on Top Layer "Top Layer-MU" (solid, remove dead copper, pour order 66): 2428.8,544.02 2428.8,500.02 2425.8,497.02 2338.8,497.02 2334.8,501.02 2334.8,605.02 2337.8,608.02 2424.8,608.02 2428.8,604.02
NetC24_1 on Top Layer "Top Layer-MU" (solid, remove dead copper, pour order 68): 1580,623 1563,606 1374,606 1370,610 1370,689 1380,699 1559,699 1573,685 1573,645 1580,638 1643.74,638 1645.74,636 1645.74,624.74 1644,623
GND on Top Layer "Top Layer-MU" (solid, remove dead copper, pour order 72): 18 vertices, not listed, extent 1348,539 1637.64,583
VDD_5.3V on Top Layer "Top Layer-MU" (solid, remove dead copper, pour order 76): 1346,602 1257,602 1253.26,605.74 1253.26,688.52 1257.73,693 1344,693 1349,688 1349,605
VREF_5V on Top Layer "Top Layer-MU" (solid, remove dead copper, pour order 78): 459.42,6277.3 459.42,6122.64 465.76,6116.3 544.76,6116.3 550.76,6122.3 550.76,6277.3 545.93,6282.13 461.24,6282.13 459.42,6280.3
NetC36_1 on Top Layer "Top Layer-MU" (solid, remove dead copper, pour order 82): 450.77,6373.07 433.77,6356.07 298.77,6356.07 296.77,6358.08 296.77,6455.31 306.76,6465.3 413.54,6465.3 443.77,6435.07 443.77,6395.07 450.77,6388.07 514.5,6388.07 516.5,6386.07 516.5,6374.81 514.77,6373.07
GND on Top Layer "Top Layer-MU" (solid, remove dead copper, pour order 88): 19 vertices, not listed, extent 308.76,6118.3 508.41,6333.3
NetC7_2 on Top Layer "Top Layer-MU" (solid, remove dead copper, pour order 162): 282.37,571.02 105.37,571.02 105.37,697.02 115.37,707.02 221.37,707.02 224.37,707.02 227.37,704.02 227.37,631.94 238.28,621.02 359.37,621.02 368.37,612.02 368.37,574.05 361.61,567.29 321.1,567.29 317.37,571.02
GND on Top Layer "Top Layer-MU" (solid, remove dead copper, pour order 164): 23 vertices, not listed, extent 243.63,437 463.63,707.02
GND on Top Layer "Top Layer-MU" (solid, remove dead copper, pour order 194): 1417,4401 1417,4273 1424,4266 1539,4266 1543,4270 1543,4495 1533,4505 1470,4505 1466,4501 1466,4425.34 1455,4414.34 1420.34,4414.34 1417,4411
NetC59_1 on Top Layer "Top Layer-MU" (solid, remove dead copper, pour order 196): 1386,3962 1264,3962 1255,3953 1255,3820 1262,3813 1313,3813 1317,3817 1317,3889 1320,3892 1395.13,3892 1395.13,3958.87 1392,3962
NetC47_1 on Top Layer "Top Layer-MU" (solid, remove dead copper, pour order 262): 1311,2170.43 1189,2170.43 1180,2161.43 1180,2028.43 1187,2021.43 1238,2021.43 1242,2025.43 1242,2097.43 1245,2100.43 1320.13,2100.43 1320.13,2167.3 1317,2170.43
GND on Top Layer "Top Layer-MU" (solid, remove dead copper, pour order 296): 1417,7992.01 1417,7864.01 1424,7857.01 1539,7857.01 1543,7861.01 1543,8086.01 1533,8096.01 1470,8096.01 1466,8092.01 1466,8016.35 1455,8005.35 1420.34,8005.35 1417,8002.01
NetC85_1 on Top Layer "Top Layer-MU" (solid, remove dead copper, pour order 300): 1386,7553.01 1264,7553.01 1255,7544.01 1255,7411.01 1262,7404.01 1313,7404.01 1317,7408.01 1317,7480.01 1320,7483.01 1395.13,7483.01 1395.13,7549.88 1392,7553.01
GND on Top Layer "Top Layer-MU" (solid, remove dead copper, pour order 306): 1341.15,6196.12 1341.15,6068.12 1348.15,6061.12 1463.15,6061.12 1467.15,6065.12 1467.15,6290.12 1457.15,6300.12 1394.15,6300.12 1390.15,6296.12 1390.15,6220.46 1379.15,6209.46 1344.49,6209.46 1341.15,6206.12
NetC72_1 on Top Layer "Top Layer-MU" (solid, remove dead copper, pour order 310): 1311,5761.43 1189,5761.43 1180,5752.43 1180,5619.43 1187,5612.43 1238,5612.43 1242,5616.43 1242,5688.43 1245,5691.43 1320.13,5691.43 1320.13,5758.31 1317,5761.43
CLK_1.8V on Top Layer "Top Layer-MU" (solid, remove dead copper, pour order 472): 35,750 35,620 40,615 85,615 90,620 90,745 85,750 40,750 35,745
VCC-P1 on Top Layer "h" (solid, remove dead copper, pour order 600): 25 vertices, not listed, extent 1413,3567 1738,3961
GND on Top Layer "h" (solid, remove dead copper, pour order 604): 27 vertices, not listed, extent 1338,3525 1654,3755
GND on Top Layer "h" (solid, remove dead copper, pour order 610): 30 vertices, not listed, extent 1303.26,1699.2 1582,1975
GND on Top Layer "h" (solid, remove dead copper, pour order 612): 30 vertices, not listed, extent 1303.26,5290.21 1582,5566.01
GND on Top Layer "h" (solid, remove dead copper, pour order 618): 27 vertices, not listed, extent 1338,7116.01 1654,7346.01
VCC-P2 on Top Layer "h" (solid, remove dead copper, pour order 622): 25 vertices, not listed, extent 1411.9,7153.8 1736.9,7547.8
GND on Top Layer "Top Layer-MU" (solid, remove dead copper, pour order 258): 1341.15,2605.11 1341.15,2477.11 1348.15,2470.11 1463.15,2470.11 1467.15,2474.11 1467.15,2699.11 1457.15,2709.11 1394.15,2709.11 1390.15,2705.11 1390.15,2629.45 1379.15,2618.45 1344.49,2618.45 1341.15,2615.11
VIN1 on Top Layer "h" (solid, remove dead copper, pour order 780): 22 vertices, not listed, extent 635,630 1375,1055
VIN1 on Top Layer "h" (solid, remove dead copper, pour order 782): 48 vertices, not listed, extent 2525,755 5770,1405
NetU9_6 on Top Layer "h" (solid, remove dead copper, pour order 4): 24 vertices, not listed, extent 5088,579 5477,735
A_VOUT on Top Layer "Top Layer-MU" (solid, remove dead copper, pour order 12): 53 vertices, not listed, extent 5018,100 5665,1061
GND on Top Layer "h" (solid, remove dead copper, pour order 638): 2755,4330 2755,4405 2735,4425 2650,4425 2640,4435 2635,4440 2635,4485 2650,4500 2785,4500 2810,4475 2810,4310 2805,4305 2765,4305 2760,4305 2755,4310
NetC130_2 on Top Layer "h" (solid, remove dead copper, pour order 842): 4487.91,6891.01 4487.91,7196.01 4482.91,7201.01 4392.91,7201.01 4387.91,7196.01 4387.91,6891.01 4397.91,6881.01 4477.91,6881.01
NetC128_1 on Top Layer "h" (solid, remove dead copper, pour order 844): 4375,8466.01 4375,8161.01 4380,8156.01 4470,8156.01 4475,8161.01 4475,8466.01 4465,8476.01 4385,8476.01
NetC130_1 on Top Layer "h" (solid, remove dead copper, pour order 846): 4665,7321.01 4175,7321.01 4165,7311.01 4165,7236.01 4170,7231.01 4685,7231.01 4695,7241.01 4695,7311.01 4685,7321.01
NetC128_2 on Top Layer "h" (solid, remove dead copper, pour order 848): 4665,8121.01 4175,8121.01 4165,8111.01 4165,8036.01 4170,8031.01 4685,8031.01 4695,8041.01 4695,8111.01 4685,8121.01
NetC123_2 on Top Layer "h" (solid, remove dead copper, pour order 850): 4665,6325.5 4175,6325.5 4165,6315.5 4165,6240.5 4170,6235.5 4685,6235.5 4695,6245.5 4695,6315.5 4685,6325.5
NetC125_1 on Top Layer "h" (solid, remove dead copper, pour order 852): 4665,5525.5 4175,5525.5 4165,5515.5 4165,5440.5 4170,5435.5 4685,5435.5 4695,5445.5 4695,5515.5 4685,5525.5
NetC123_1 on Top Layer "h" (solid, remove dead copper, pour order 854): 4375,6670.5 4375,6365.5 4380,6360.5 4470,6360.5 4475,6365.5 4475,6670.5 4465,6680.5 4385,6680.5
NetC125_2 on Top Layer "h" (solid, remove dead copper, pour order 856): 4487.91,5095.5 4487.91,5400.5 4482.91,5405.5 4392.91,5405.5 4387.91,5400.5 4387.91,5095.5 4397.91,5085.5 4477.91,5085.5
NetC118_2 on Top Layer "h" (solid, remove dead copper, pour order 858): 4665,4530 4175,4530 4165,4520 4165,4445 4170,4440 4685,4440 4695,4450 4695,4520 4685,4530
NetC120_1 on Top Layer "h" (solid, remove dead copper, pour order 860): 4665,3730 4175,3730 4165,3720 4165,3645 4170,3640 4685,3640 4695,3650 4695,3720 4685,3730
NetC118_1 on Top Layer "h" (solid, remove dead copper, pour order 862): 4375,4875 4375,4570 4380,4565 4470,4565 4475,4570 4475,4875 4465,4885 4385,4885
NetC120_2 on Top Layer "h" (solid, remove dead copper, pour order 864): 4487.91,3300 4487.91,3605 4482.91,3610 4392.91,3610 4387.91,3605 4387.91,3300 4397.91,3290 4477.91,3290
NetC115_2 on Top Layer "h" (solid, remove dead copper, pour order 898): 4487.91,1504.5 4487.91,1809.5 4482.91,1814.5 4392.91,1814.5 4387.91,1809.5 4387.91,1504.5 4397.91,1494.5 4477.91,1494.5
NetC113_1 on Top Layer "h" (solid, remove dead copper, pour order 900): 4375,3079.5 4375,2774.5 4380,2769.5 4470,2769.5 4475,2774.5 4475,3079.5 4465,3089.5 4385,3089.5
NetC115_1 on Top Layer "h" (solid, remove dead copper, pour order 902): 4665,1934.5 4175,1934.5 4165,1924.5 4165,1849.5 4170,1844.5 4685,1844.5 4695,1854.5 4695,1924.5 4685,1934.5
NetC113_2 on Top Layer "h" (solid, remove dead copper, pour order 904): 4665,2734.5 4175,2734.5 4165,2724.5 4165,2649.5 4170,2644.5 4685,2644.5 4695,2654.5 4695,2724.5 4685,2734.5
NetF2_2 on Top Layer "Top Layer-No Net" (solid, pour order 906): 388,1834 388,1755 398,1745 410,1733 490,1733 611,1733 615,1737 615,1884 609,1890 416,1890 388,1862
NetD14_3 on Top Layer "h" (solid, remove dead copper, pour order 942): 4815,6215.5 4815,6310.01 4838,6333.01 5079,6333.01 5148,6264.01 5148,5599.01 4973.21,5424.22 4825,5424.22 4810,5439.22 4810,5550.5 4875,5615.5 4875,6155.5
NetD20_1 on Top Layer "h" (solid, remove dead copper, pour order 964): 4815,8017.5 4815,8112.01 4838,8135.01 5079,8135.01 5148,8066.01 5148,7401.01 4973.21,7226.22 4825,7226.22 4810,7241.22 4810,7352.5 4875,7417.5 4875,7957.5
NetU7_34 on Top Layer "Top Layer-No Net" (solid, pour order 974): 3235,881 3235,849 3237,847 3315,847 3414,847 3417,850 3417,872 3417,885 3414,888 3242,888 3239,888 3235,884
NetU8_34 on Top Layer "Top Layer-No Net" (solid, pour order 976): 4244,872.27 4244,840.27 4246,838.27 4324,838.27 4423,838.27 4426,841.27 4426,863.27 4426,876.27 4423,879.27 4251,879.27 4248,879.27 4244,875.27
VOUT-N1 on Bottom Layer "Top Layer-No Net 1" (solid, pour order 1056): 32 vertices, not listed, extent 5251,1899 6408,2701
VOUT-P1 on Bottom Layer "Top Layer-No Net 1" (solid, pour order 1052): 30 vertices, not listed, extent 5230,3693 6407.7,4497
GND on Bottom Layer "h" (solid, remove dead copper, pour order 1028): 17 vertices, not listed, extent 3999.56,1645 6408,3099.5
GND on Bottom Layer "h" (solid, remove dead copper, pour order 1018): 17 vertices, not listed, extent 3999.26,3441 6409.26,4895.5
VOUT-N2 on Bottom Layer "Top Layer-No Net 1" (solid, pour order 1012): 32 vertices, not listed, extent 5251,5494 6408,6292
VOUT-P2 on Bottom Layer "Top Layer-No Net 1" (solid, pour order 1010): 31 vertices, not listed, extent 5267,7183 6410,8028
NetC82_1 on Bottom Layer "h" (solid, remove dead copper, pour order 770): 25 vertices, not listed, extent 2535,7071.01 3455,7386.01
NetC82_2 on Bottom Layer "h" (solid, remove dead copper, pour order 768): 2510,7181.01 2405,7181.01 2400,7176.01 2400,7121.01 2400,7116.01 2405,7111.01 2510,7111.01 2515,7116.01 2515,7176.01
GND on Bottom Layer "h" (solid, remove dead copper, pour order 766): 2490,7256.01 2404.5,7256.01 2380,7231.51 2380,7116.46 2375,7111.46 2329.54,7111.46 2325,7116.01 2325,7306.01 2340,7321.01 2350,7331.01 2490,7331.01 2500,7331.01 2505,7326.01 2505,7261.01 2500,7256.01
NetC128_2 on Bottom Layer "h" (solid, remove dead copper, pour order 764): 4665,8121.01 4175,8121.01 4165,8111.01 4165,8036.01 4170,8031.01 4685,8031.01 4695,8041.01 4695,8111.01 4685,8121.01
NetC130_1 on Bottom Layer "h" (solid, remove dead copper, pour order 762): 4665,7321.01 4175,7321.01 4165,7311.01 4165,7236.01 4170,7231.01 4685,7231.01 4695,7241.01 4695,7311.01 4685,7321.01
NetC128_1 on Bottom Layer "h" (solid, remove dead copper, pour order 760): 4375,8466.01 4375,8161.01 4380,8156.01 4470,8156.01 4475,8161.01 4475,8466.01 4465,8476.01 4385,8476.01
NetC130_2 on Bottom Layer "h" (solid, remove dead copper, pour order 758): 4487.91,6891.01 4487.91,7196.01 4482.91,7201.01 4392.91,7201.01 4387.91,7196.01 4387.91,6891.01 4397.91,6881.01 4477.91,6881.01
GND on Bottom Layer "h" (solid, remove dead copper, pour order 752): 3990,7711.01 3990,6881.01 4000,6871.01 4070,6871.01 4090,6891.01 4090,7536.01 4145,7591.01 4145,7711.01
NetC69_1 on Bottom Layer "h" (solid, remove dead copper, pour order 736): 25 vertices, not listed, extent 2534.15,5275.12 3454.15,5590.12
GND on Bottom Layer "h" (solid, remove dead copper, pour order 734): 3990,5915.5 3990,5085.5 4000,5075.5 4070,5075.5 4090,5095.5 4090,5740.5 4145,5795.5 4145,5915.5
NetC125_2 on Bottom Layer "h" (solid, remove dead copper, pour order 728): 4487.91,5095.5 4487.91,5400.5 4482.91,5405.5 4392.91,5405.5 4387.91,5400.5 4387.91,5095.5 4397.91,5085.5 4477.91,5085.5
NetC123_1 on Bottom Layer "h" (solid, remove dead copper, pour order 726): 4375,6670.5 4375,6365.5 4380,6360.5 4470,6360.5 4475,6365.5 4475,6670.5 4465,6680.5 4385,6680.5
NetC125_1 on Bottom Layer "h" (solid, remove dead copper, pour order 724): 4665,5525.5 4175,5525.5 4165,5515.5 4165,5440.5 4170,5435.5 4685,5435.5 4695,5445.5 4695,5515.5 4685,5525.5
NetC123_2 on Bottom Layer "h" (solid, remove dead copper, pour order 722): 4665,6325.5 4175,6325.5 4165,6315.5 4165,6240.5 4170,6235.5 4685,6235.5 4695,6245.5 4695,6315.5 4685,6325.5
GND on Bottom Layer "h" (solid, remove dead copper, pour order 720): 2489.15,5460.12 2403.65,5460.12 2379.15,5435.62 2379.15,5320.58 2374.15,5315.58 2328.69,5315.58 2324.15,5320.12 2324.15,5510.12 2339.15,5525.12 2349.15,5535.12 2489.15,5535.12 2499.15,5535.12 2504.15,5530.12 2504.15,5465.12 2499.15,5460.12
NetC69_2 on Bottom Layer "h" (solid, remove dead copper, pour order 718): 2509.15,5385.12 2404.15,5385.12 2399.15,5380.12 2399.15,5325.12 2399.15,5320.12 2404.15,5315.12 2509.15,5315.12 2514.15,5320.12 2514.15,5380.12
NetC44_1 on Bottom Layer "h" (solid, remove dead copper, pour order 692): 25 vertices, not listed, extent 2534.15,1684.11 3454.15,1999.11
NetC44_2 on Bottom Layer "h" (solid, remove dead copper, pour order 690): 2509.15,1794.11 2404.15,1794.11 2399.15,1789.11 2399.15,1734.11 2399.15,1729.11 2404.15,1724.11 2509.15,1724.11 2514.15,1729.11 2514.15,1789.11
GND on Bottom Layer "h" (solid, remove dead copper, pour order 688): 2489.15,1869.11 2403.65,1869.11 2379.15,1844.61 2379.15,1729.57 2374.15,1724.57 2328.69,1724.57 2324.15,1729.11 2324.15,1919.11 2339.15,1934.11 2349.15,1944.11 2489.15,1944.11 2499.15,1944.11 2504.15,1939.11 2504.15,1874.11 2499.15,1869.11
NetC113_2 on Bottom Layer "h" (solid, remove dead copper, pour order 686): 4665,2734.5 4175,2734.5 4165,2724.5 4165,2649.5 4170,2644.5 4685,2644.5 4695,2654.5 4695,2724.5 4685,2734.5
NetC115_1 on Bottom Layer "h" (solid, remove dead copper, pour order 684): 4665,1934.5 4175,1934.5 4165,1924.5 4165,1849.5 4170,1844.5 4685,1844.5 4695,1854.5 4695,1924.5 4685,1934.5
NetC113_1 on Bottom Layer "h" (solid, remove dead copper, pour order 682): 4375,3079.5 4375,2774.5 4380,2769.5 4470,2769.5 4475,2774.5 4475,3079.5 4465,3089.5 4385,3089.5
